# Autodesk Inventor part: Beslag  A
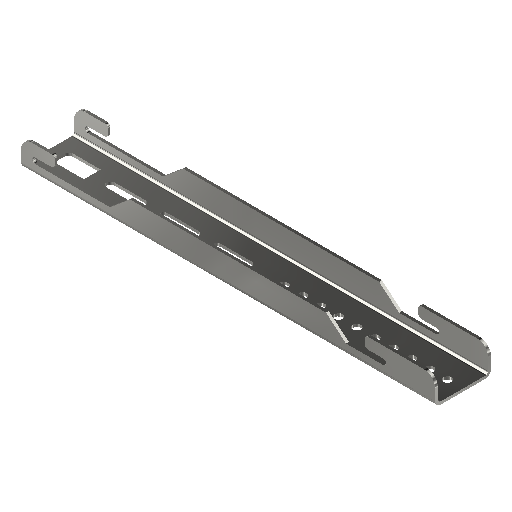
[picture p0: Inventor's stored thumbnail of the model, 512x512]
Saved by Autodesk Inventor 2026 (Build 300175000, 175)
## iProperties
Created: 2013-10
Part Number: Beslag  A
Material: Steel, Mild
Document SubType Name: Modeling
Designer: Lars Bertram Pedersen
Density: 7.85 g/cm^3
Appearance: Silver
Mass: 294.694 g
Surface Area: 402.313 cm^2
Volume: 37.5406 cm^3
Stock Number: 2005
Author: Lars Bertram Pedersen
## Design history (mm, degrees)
sketch "Sketch1"
  geometry: L1 (-148, 0)-(148, 0); L2 (148, 0)-(148, 20); L3 (148, 20)-(124, 20); L4 (124, 20)-(124, 12); L5 (124, 12)-(138, 12); L6 (138, 8)-(84.301, 8); L7 (84.301, 8)-(70, 20); L8 (70, 20)-(-70, 20); L9 (-70, 20)-(-84.301, 8); L10 (-84.301, 8)-(-111, 8); L11 (-111, 12)-(-98, 12); L12 (-98, 12)-(-98, 20); L13 (-148, 20)-(-148, 0); L14 (-148, 20)-(-98, 20); L15 (0, 0)-(0, 20); A1 r 2 centre (138, 10) between (138, 8) and (138, 12); A2 r 2 centre (-111, 10) between (-111, 12) and (-111, 8); 2 further points
  constraints: 30 end point, 8 parallel, 5 perpendicular, 4 point on circle, 4 tangent, 3 collinear, 2 centre point, 2 coincident, 2 midpoint, 2 point on line, 1 horizontal, 1 other
  dimensions: "d0" = 296 distance of L1.start L1.end; "d3" = 50 distance of L13.start L12.end; "d7" = 8 distance between parallel lines of L1 L6; "d8" = 8 distance of L3.end L4.end; "d11" = 20 distance between parallel lines of L1 L3; "d21" = 8 distance edge to line of A1 L2; "d22" = 24 distance between parallel lines of L2 L4; "d24" = 35 distance edge to line of A2 L13; "d28" = 140 distance of L7.end L8.end; "d29" = 78 distance of L2.end L7.end (derived); "d30" = 78 distance of L13.start L8.end (derived); "d31" = 4 distance between parallel lines of L5 L6 (derived); "d32" = 140 deg angle of L7 L6
extrude "Extrusion1" new body sketch "Sketch1" stored distance "d33" = 40; taper "d34" = 0 deg
sketch "Sketch2"
  geometry: L1 (40, 20)-(0, 20) reference; L2 (0, 0)-(0, 20) reference; L3 (40, 0)-(0, 0) reference; L4 (40, 20)-(40, 0) reference; L5 (38, 20)-(38, 2); L6 (38, 2)-(2, 2); L7 (2, 2)-(2, 20); L8 (38, 20)-(40, 20); L9 (2, 20)-(0, 20); 1 further point
  constraints: 10 end point, 2 point on line, 1 collinear, 1 perpendicular
  dimensions: "d35" = 2 distance between parallel lines of L2 L7; "d90" = 2 distance between parallel lines of L3 L6 (= d35); "d91" = 2 distance between parallel lines of L4 L5 (= d35)
extrude "Extrusion2" sketch "Sketch2" extent not by distance; stored distance "d36" = 40; taper "d37" = 0 deg
sketch "Sketch5"
  geometry: L1 (-296, 36)-(-296, 0) reference; 3 further points
  constraints: 1 horizontal alignment, 1 midpoint
  dimensions: "d43" = 11 distance of point (-296, 18) point (-285, 18)
hole "Hole2" sketch "Sketch5" diameter "d51" = 6; stored, may be unused: countersink angle "d55" = 90 deg, drill point angle "d57" = 118 deg; dims "d52" = 6, "d53" = 4, "d54" = 2, "d56" = 8
pattern_linear "Rectangular Pattern1" dims "d60" = 13
sketch "Sketch7"
  geometry: L1 (0, 0)-(0, 36) reference; L2 (-31, 24)-(-8, 24); L3 (-8, 24)-(-8, 12); L4 (-8, 12)-(-31, 12); L5 (-31, 12)-(-31, 24); 5 further points
  constraints: 8 end point, 4 midpoint, 2 parallel, 1 horizontal, 1 horizontal alignment, 1 perpendicular
  dimensions: "d63" = 12 distance between parallel lines of L4 L2; "d64" = 23 distance of L2.start L2.end; "d65" = 8 distance between parallel lines of L1 L3
extrude "Extrusion3" cut sketch "Sketch7" distance "d74" = 40; taper "d75" = 0 deg
sketch "Sketch8"
  geometry: L1 (31, 24)-(31, 12) reference; L2 (31, 12)-(8, 12) reference; L3 (0, 36)-(0, 0) reference; L4 (41, 18)-(69, 18); L5 (44, 15)-(66, 15); L6 (66, 21)-(44, 21); A1 r 3 centre (44, 18) between (44, 21) and (44, 15); A2 r 3 centre (66, 18) between (66, 15) and (66, 21); 3 further points
  constraints: 8 end point, 6 point on circle, 4 tangent, 2 centre point, 2 midpoint, 2 parallel, 2 point on line, 1 horizontal alignment
  dimensions: "d78" = 28 distance of L4.start L4.end; "d79" = 6 diameter of A2; "d80" = 10 distance from line of L4.start L1
extrude "Extrusion4" cut sketch "Sketch8" extent not by distance; stored distance "d81" = 40; taper "d82" = 0 deg
pattern_linear "Rectangular Pattern2" dims "d85" = 38
fillet "Fillet1" dims "d38" = 4
fillet "Fillet2" dims "d39" = 2
fillet "Fillet3" dims "d40" = 2
fillet "Fillet4" dims "d41" = 8
fillet "Fillet5" dims "d86" = 3
body "Solid1"
